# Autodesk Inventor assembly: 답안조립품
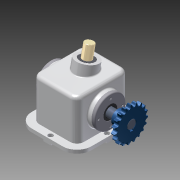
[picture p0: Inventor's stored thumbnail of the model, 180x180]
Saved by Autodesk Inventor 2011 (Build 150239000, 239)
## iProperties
Created: 2014-11
Part Number: 답안조립품
Document SubType Name: Assembly
Designer: Administrator
Author: Administrator
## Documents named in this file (13)
- C:\Documents and Settings\Administrator\바탕 화면\441122V1011\답안조립품.iam
- C:\Documents and Settings\Administrator\바탕 화면\441122V1011\본체.ipt
- C:\Documents and Settings\Administrator\바탕 화면\441122V1011\편심축.ipt
- C:\Documents and Settings\Administrator\바탕 화면\441122V1011\5-체인 스프로킷.ipt
- C:\Documents and Settings\Administrator\바탕 화면\441122V1011\키 8x8.ipt
- C:\Documents and Settings\Administrator\바탕 화면\441122V1011\멈춤나사 M5x0.5.ipt
- C:\Documents and Settings\Administrator\바탕 화면\441122V1011\베어링 6205.ipt
- C:\Documents and Settings\Administrator\바탕 화면\441122V1011\뒤커버.ipt
- C:\Documents and Settings\Administrator\바탕 화면\441122V1011\앞커버.ipt
- C:\Documents and Settings\Administrator\바탕 화면\441122V1011\부시.ipt
- C:\Documents and Settings\Administrator\바탕 화면\441122V1011\오일실.ipt
- C:\Documents and Settings\Administrator\바탕 화면\441122V1011\슬라이드.ipt
- C:\Documents and Settings\Administrator\바탕 화면\441122V1011\M4x0.5.ipt
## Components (9 placed, 2 different names)
1. 5-체인 스프로킷:1
2. M4x0.5:1
3. M4x0.5:3
4. M4x0.5:4
5. M4x0.5:5
6. M4x0.5:2
7. M4x0.5:6
8. M4x0.5:7
9. M4x0.5:8
